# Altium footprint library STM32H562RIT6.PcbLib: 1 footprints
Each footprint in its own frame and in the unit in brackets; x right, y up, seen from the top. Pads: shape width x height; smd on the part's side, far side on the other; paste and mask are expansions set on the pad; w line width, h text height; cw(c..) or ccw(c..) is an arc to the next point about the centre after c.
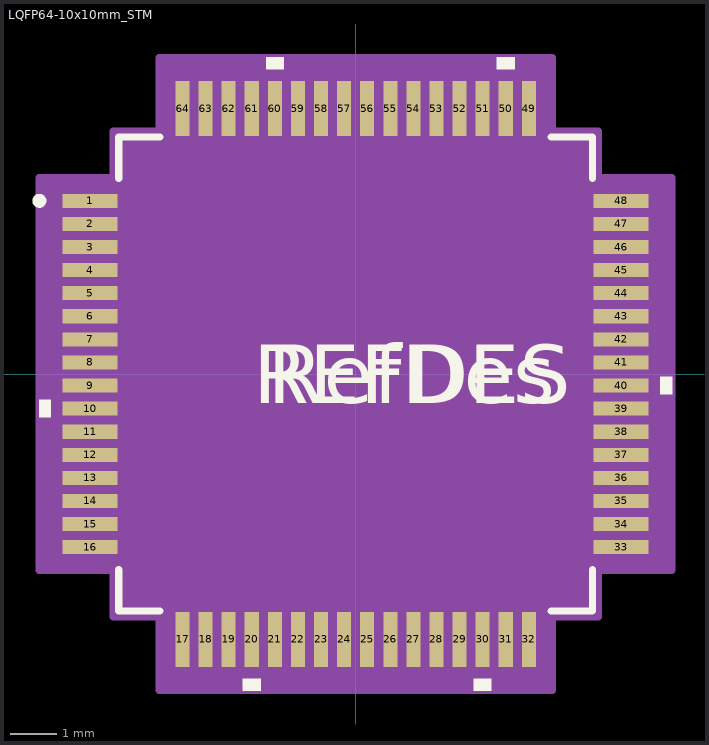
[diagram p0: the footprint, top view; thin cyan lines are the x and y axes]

## LQFP64-10x10mm_STM [mm]
pads (64):
  rect 1.194x0.305 smd paste+0 mask+0: 1(-5.75,3.75) 2(-5.75,3.25) 3(-5.75,2.75) 4(-5.75,2.25) 5(-5.75,1.75) 6(-5.75,1.25) 7(-5.75,0.75) 8(-5.75,0.25) 9(-5.75,-0.25) 10(-5.75,-0.75) 11(-5.75,-1.25) 12(-5.75,-1.75) 13(-5.75,-2.25) 14(-5.75,-2.75) 15(-5.75,-3.25) 16(-5.75,-3.75) 33(5.75,-3.75) 34(5.75,-3.25) 35(5.75,-2.75) 36(5.75,-2.25) 37(5.75,-1.75) 38(5.75,-1.25) 39(5.75,-0.75) 40(5.75,-0.25) 41(5.75,0.25) 42(5.75,0.75) 43(5.75,1.25) 44(5.75,1.75) 45(5.75,2.25) 46(5.75,2.75) 47(5.75,3.25) 48(5.75,3.75)
  rect 0.305x1.194 smd paste+0 mask+0: 17(-3.75,-5.75) 18(-3.25,-5.75) 19(-2.75,-5.75) 20(-2.25,-5.75) 21(-1.75,-5.75) 22(-1.25,-5.75) 23(-0.75,-5.75) 24(-0.25,-5.75) 25(0.25,-5.75) 26(0.75,-5.75) 27(1.25,-5.75) 28(1.75,-5.75) 29(2.25,-5.75) 30(2.75,-5.75) 31(3.25,-5.75) 32(3.75,-5.75) 49(3.75,5.75) 50(3.25,5.75) 51(2.75,5.75) 52(2.25,5.75) 53(1.75,5.75) 54(1.25,5.75) 55(0.75,5.75) 56(0.25,5.75) 57(-0.25,5.75) 58(-0.75,5.75) 59(-1.25,5.75) 60(-1.75,5.75) 61(-2.25,5.75) 62(-2.75,5.75) 63(-3.25,5.75) 64(-3.75,5.75)
Top Overlay:
  circle w0.152: c-6.851,3.75 r0.076
  region: -6.601,-0.56 -6.855,-0.56 -6.855,-0.941 -6.601,-0.941
  region: -2.06,-6.601 -2.441,-6.601 -2.441,-6.855 -2.06,-6.855
  region: 2.94,-6.601 2.559,-6.601 2.559,-6.855 2.94,-6.855
  region: 6.601,-0.059 6.855,-0.059 6.855,-0.44 6.601,-0.44
  region: 3.441,6.601 3.06,6.601 3.06,6.855 3.441,6.855
  region: -1.559,6.601 -1.94,6.601 -1.94,6.855 -1.559,6.855
  lines w0.152: -5.131,-4.234 -5.131,-5.131 -4.234,-5.131 ; -5.131,4.234 -5.131,5.131 -4.234,5.131 ; 4.234,-5.131 5.131,-5.131 5.131,-4.234 ; 4.234,5.131 5.131,5.131 5.131,4.234
  text "RefDes" at -1.905,-0.635 h1.27
  text "REFDES" at -2.222,-0.635 h1.27
Mechanical 13:
  circle w0: c-4.518,3.75 r0.076
  lines w0.025: -5.004,3.734 -3.734,5.004 ; -5.004,-5.004 5.004,-5.004 5.004,5.004 -5.004,5.004 -5.004,-5.004
  text "RefDes2" at -2.222,-0.635 h1.27
Mechanical 15:
  region: -4.258,-5.258 -5.258,-5.258 -5.258,-4.258 -6.855,-4.258 -6.855,4.258 -5.258,4.258 -5.258,5.258 -4.258,5.258 -4.258,6.855 4.258,6.855 4.258,5.258 5.258,5.258 5.258,4.258 6.855,4.258 6.855,-4.258 5.258,-4.258 5.258,-5.258 4.258,-5.258 4.258,-6.855 -4.258,-6.855
  lines w0.152: -6.855,-4.258 -5.258,-4.258 -5.258,-5.258 -4.258,-5.258 -4.258,-6.855 4.258,-6.855 4.258,-5.258 5.258,-5.258 5.258,-4.258 6.855,-4.258 6.855,4.258 5.258,4.258 5.258,5.258 4.258,5.258 4.258,6.855 -4.258,6.855 -4.258,5.258 -5.258,5.258 -5.258,4.258 -6.855,4.258 -6.855,-4.258
3D body "LQFP64-10x10mm_STM.step": height 1.6, standoff 0, extent -5.997,-5.997 5.997,5.997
